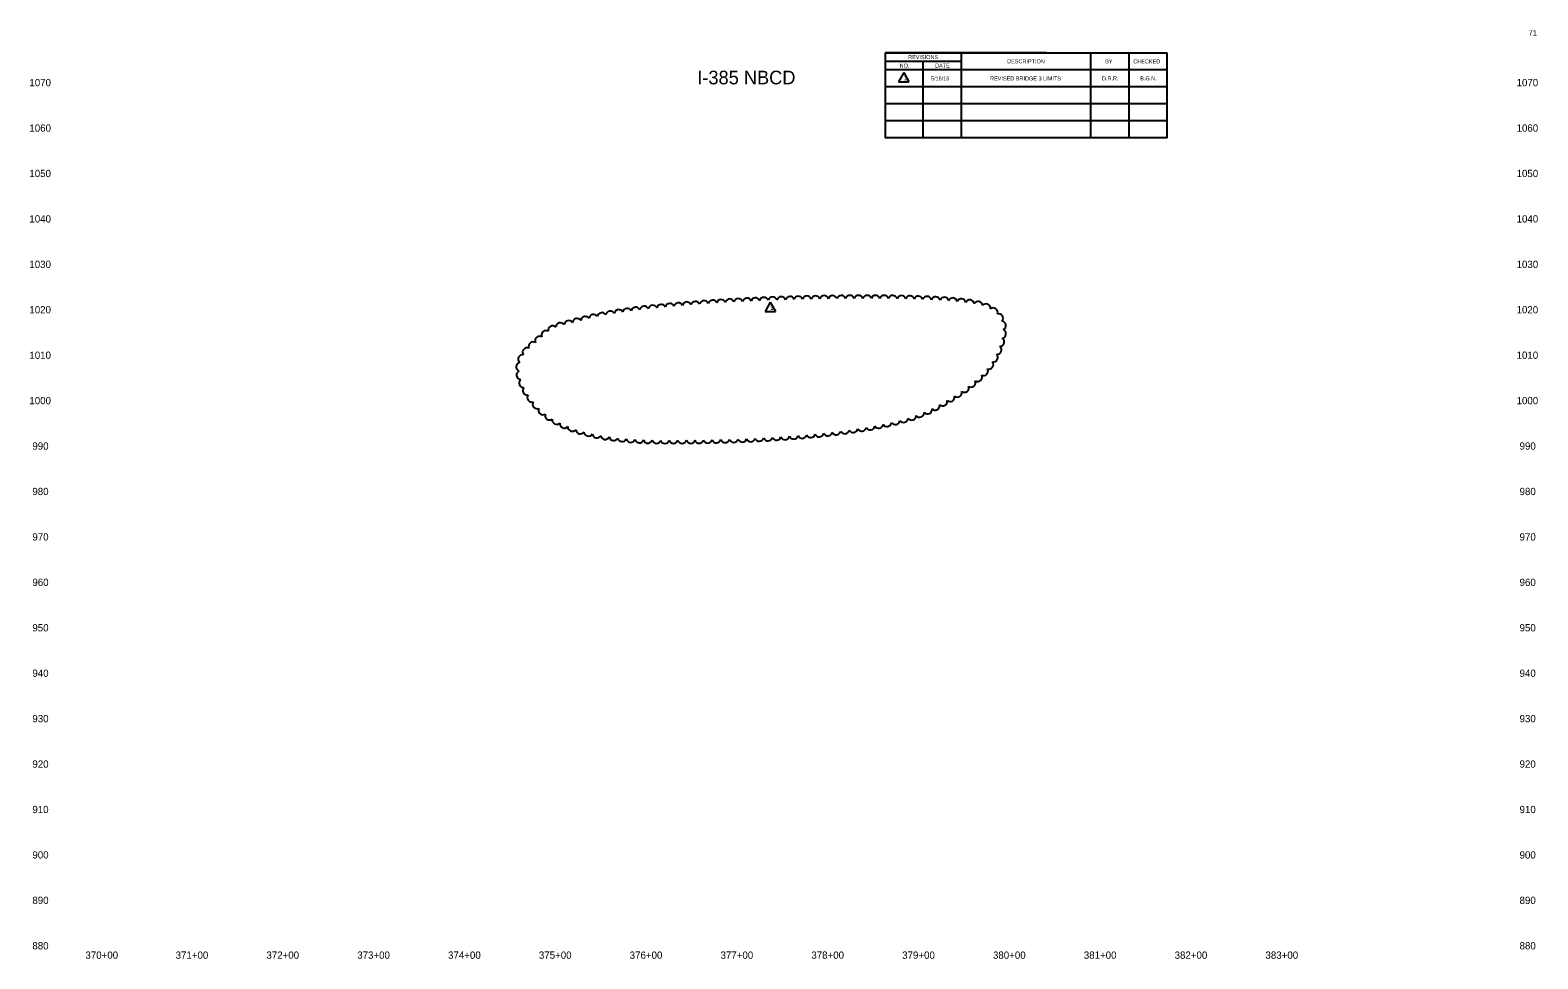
# Model space of a CAD drawing. Extents: x 16977137 to 16978798, y 12564177 to 12565200.
import ezdxf

# ---------------------------------------------------------------- set-up
doc = ezdxf.new("R2010")
doc.units = 0
for name, color, linetype in [('RD_DDB_ElevTX', 7, 'Continuous'), ('RD_DDB_StaTX', 7, 'Continuous'), ('RD_SHT_TX', 7, 'Continuous')]:
    doc.layers.add(name, color=color, linetype=linetype)

msp = doc.modelspace()

# ---------------------------------------------------------------- linework, layer by layer
at = {"layer": 'RD_SHT_TX'}
for p, q in [((16978078.8, 12565174.6), (16978389.4, 12565174.6)), ((16978256, 12565174.6), (16978078.8, 12565174.6)), ((16978078.8, 12565174.6), (16978078.8, 12565081.1)), ((16978162.8, 12565081.1), (16978162.8, 12565174.6)), ((16978305.4, 12565081.1), (16978305.4, 12565174.6)), ((16978347.4, 12565081.1), (16978347.4, 12565174.6)), ((16978389.4, 12565081), (16978389.4, 12565174.5)), ((16978162.8, 12565165.2), (16978078.8, 12565165.2)), ((16978389.4, 12565155.9), (16978078.8, 12565155.9)), ((16978120.8, 12565081.1), (16978120.8, 12565165.2)), ((16978099.4, 12565152.9), (16978093.7, 12565142.7)), ((16978093.7, 12565142.7), (16978105.1, 12565142.7)), ((16978099.4, 12565152.9), (16978105.1, 12565142.7)), ((16978389.4, 12565137.2), (16978078.8, 12565137.2)), ((16978389.4, 12565118.5), (16978078.8, 12565118.5)), ((16978389.4, 12565099.8), (16978078.8, 12565099.8)), ((16978389.4, 12565081), (16978078.8, 12565081.1)), ((16977952.4, 12564900.2), (16977946.8, 12564890)), ((16977946.8, 12564890), (16977958.1, 12564890)), ((16977952.4, 12564900.2), (16977958.1, 12564890))]:
    msp.add_line(p, q, dxfattribs=at)
for centre, radius, start, end in [((16977945.5, 12564900.5), 4.96, 19.8292, 164.8292), ((16977955, 12564900.9), 4.96, 19.6052, 164.6052), ((16977964.4, 12564901.2), 4.96, 19.388, 164.388), ((16977973.9, 12564901.5), 4.96, 19.1772, 164.1772), ((16977983.3, 12564901.8), 4.96, 18.9726, 163.9726), ((16977992.8, 12564902), 4.96, 18.7739, 163.7739), ((16978002.2, 12564902.2), 4.96, 18.5808, 163.5808), ((16978011.7, 12564902.4), 4.96, 18.3931, 163.3931), ((16978021.1, 12564902.5), 4.96, 18.2104, 163.2104), ((16978030.6, 12564902.6), 4.96, 18.0327, 163.0327), ((16978040, 12564902.7), 4.96, 17.8596, 162.8596), ((16978049.5, 12564902.7), 4.96, 17.691, 162.691), ((16978058.9, 12564902.7), 4.96, 17.5232, 162.5232), ((16978068.4, 12564902.7), 4.96, 17.3057, 162.3057), ((16978077.8, 12564902.7), 4.96, 17.0495, 162.0495), ((16978087.3, 12564902.6), 4.96, 16.7608, 161.7608), ((16978096.7, 12564902.4), 4.96, 16.4321, 161.4321), ((16978106.2, 12564902.2), 4.96, 16.0533, 161.0533), ((16978115.6, 12564901.9), 4.96, 15.6101, 160.6101), ((16978125.1, 12564901.6), 4.96, 15.0821, 160.0821), ((16978134.5, 12564901.1), 4.96, 14.4385, 159.4385), ((16978143.9, 12564900.6), 4.96, 13.63, 158.63), ((16977767, 12564883.7), 4.96, 28.648, 173.648), ((16977776.3, 12564885.4), 4.96, 27.371, 172.371), ((16977785.6, 12564887), 4.96, 26.3569, 171.3569), ((16977794.9, 12564888.4), 4.96, 25.5269, 170.5269), ((16977804.2, 12564889.6), 4.96, 24.8317, 169.8317), ((16977813.6, 12564890.8), 4.96, 24.2385, 169.2385), ((16977823, 12564891.8), 4.96, 23.7248, 168.7248), ((16977832.4, 12564892.8), 4.96, 23.2744, 168.2744), ((16977841.8, 12564893.7), 4.96, 22.8752, 167.8752), ((16977851.2, 12564894.6), 4.96, 22.5184, 167.5184), ((16977860.6, 12564895.4), 4.96, 22.1969, 167.1969), ((16977870, 12564896.1), 4.96, 21.9052, 166.9052), ((16977879.5, 12564896.9), 4.96, 21.6204, 166.6204), ((16977888.9, 12564897.5), 4.96, 21.3374, 166.3374), ((16977898.3, 12564898.1), 4.96, 21.0643, 166.0643), ((16977907.8, 12564898.7), 4.96, 20.8005, 165.8005), ((16977917.2, 12564899.2), 4.96, 20.5456, 165.5456), ((16977926.6, 12564899.7), 4.96, 20.299, 165.299), ((16977936.1, 12564900.1), 4.96, 20.0603, 165.0603), ((16978153.3, 12564899.8), 4.96, 12.572, 157.572), ((16978162.7, 12564898.9), 4.96, 11.1037, 156.1037), ((16978172, 12564897.7), 4.96, 8.8691, 153.8691), ((16978181.2, 12564896), 4.96, 4.8448, 149.8448), ((16978190, 12564893.3), 4.96, 356.0223, 141.0223), ((16978197.8, 12564888.9), 4.96, 341.1733, 126.1733), ((16977712.8, 12564869.2), 4.95, 46.5962, 191.5962), ((16977721.1, 12564872.5), 4.96, 31.8949, 176.8949), ((16977730.3, 12564874.9), 4.96, 31.8949, 176.8949), ((16977739.5, 12564877.2), 4.96, 31.8949, 176.8949), ((16977748.6, 12564879.5), 4.96, 31.8309, 176.8309), ((16977757.8, 12564881.8), 4.96, 30.3227, 175.3227), ((16978203.8, 12564882.5), 4.96, 319.3635, 104.3635), ((16978206.8, 12564874.4), 4.96, 296.5873, 81.5873), ((16977691.2, 12564851.4), 4.96, 58.9265, 203.9265), ((16977698.3, 12564857.7), 4.96, 58.9265, 203.9265), ((16977705.4, 12564863.9), 4.96, 58.9265, 203.9265), ((16978205.1, 12564856.4), 4.96, 271.5015, 56.5015), ((16978207, 12564865.4), 4.96, 280.3509, 65.3509), ((16977679.8, 12564837.4), 4.96, 83.1268, 228.1268), ((16977684.6, 12564844.9), 4.96, 65.8967, 210.8967), ((16978198, 12564839.3), 4.96, 258.3928, 43.3928), ((16978202.1, 12564847.7), 4.96, 265.0679, 50.0679), ((16977677.5, 12564828.9), 4.96, 102.4985, 247.4985), ((16977678, 12564819.9), 4.96, 118.7219, 263.7219), ((16978187.2, 12564824.3), 4.96, 245.3556, 30.3556), ((16978193.1, 12564831.5), 4.96, 251.7368, 36.7368), ((16977680.7, 12564811.2), 4.96, 130.0537, 275.0537), ((16977684.8, 12564802.9), 4.96, 137.7212, 282.7212), ((16978166.1, 12564805.9), 4.96, 233.4335, 18.4335), ((16978173.5, 12564811.6), 4.96, 236.1845, 21.1845), ((16978180.7, 12564817.7), 4.96, 239.6683, 24.6683), ((16977689.8, 12564795.1), 4.96, 143.0904, 288.0904), ((16977695.6, 12564787.8), 4.96, 148.0439, 293.0439), ((16978142.3, 12564790.8), 4.96, 226.919, 11.919), ((16978150.4, 12564795.6), 4.96, 228.844, 13.844), ((16978158.3, 12564800.6), 4.96, 231.0021, 16.0021), ((16977702, 12564781.2), 4.96, 155.8506, 300.8506), ((16977709.3, 12564775.5), 4.96, 162.8917, 307.8917), ((16978099.2, 12564772.7), 4.96, 213.0669, 358.0669), ((16978108.2, 12564775.4), 4.96, 215.3678, 0.3678), ((16978117, 12564778.5), 4.96, 218.3921, 3.3921), ((16978125.6, 12564782.1), 4.96, 222.4938, 7.4938), ((16978134, 12564786.3), 4.96, 225.1937, 10.1937), ((16977717.2, 12564770.6), 4.96, 168.7796, 313.7796), ((16977725.6, 12564766.5), 4.96, 173.6557, 318.6557), ((16977734.3, 12564763), 4.96, 177.6994, 322.6994), ((16977743.2, 12564760.1), 4.96, 181.0771, 326.0771), ((16977752.2, 12564757.7), 4.96, 183.9262, 328.9262), ((16978006.3, 12564756.9), 4.96, 203.3677, 348.3677), ((16978015.7, 12564758), 4.96, 203.9101, 348.9101), ((16978025, 12564759.1), 4.96, 204.4827, 349.4827), ((16978034.4, 12564760.3), 4.96, 205.1018, 350.1018), ((16978043.8, 12564761.6), 4.96, 205.7969, 350.7969), ((16978053.1, 12564763), 4.96, 206.5847, 351.5847), ((16978062.4, 12564764.5), 4.96, 207.4871, 352.4871), ((16978071.7, 12564766.3), 4.96, 208.534, 353.534), ((16978080.9, 12564768.2), 4.96, 209.7675, 354.7675), ((16978090.1, 12564770.3), 4.96, 211.2481, 356.2481), ((16977761.4, 12564755.7), 4.96, 186.355, 331.355), ((16977770.7, 12564754), 4.96, 188.4473, 333.4473), ((16977780, 12564752.7), 4.96, 190.2674, 335.2674), ((16977789.3, 12564751.6), 4.96, 191.8652, 336.8652), ((16977798.7, 12564750.8), 4.96, 193.2794, 338.2794), ((16977808.1, 12564750.2), 4.96, 194.5406, 339.5406), ((16977817.5, 12564749.8), 4.96, 195.673, 340.673), ((16977827, 12564749.6), 4.96, 196.6959, 341.6959), ((16977836.4, 12564749.5), 4.96, 197.4851, 342.4851), ((16977845.9, 12564749.6), 4.96, 197.7388, 342.7388), ((16977855.3, 12564749.6), 4.96, 197.9565, 342.9565), ((16977864.8, 12564749.7), 4.96, 198.1833, 343.1833), ((16977874.2, 12564749.8), 4.96, 198.42, 343.42), ((16977883.7, 12564750), 4.96, 198.6672, 343.6672), ((16977893.1, 12564750.2), 4.96, 198.9257, 343.9257), ((16977902.6, 12564750.5), 4.96, 199.1965, 344.1965), ((16977912, 12564750.8), 4.96, 199.4805, 344.4805), ((16977921.5, 12564751.1), 4.96, 199.7787, 344.7787), ((16977930.9, 12564751.5), 4.96, 200.0925, 345.0925), ((16977940.3, 12564752), 4.96, 200.4231, 345.4231), ((16977949.8, 12564752.5), 4.96, 200.7721, 345.7721), ((16977959.2, 12564753.1), 4.96, 201.1412, 346.1412), ((16977968.6, 12564753.7), 4.96, 201.5324, 346.5324), ((16977978, 12564754.4), 4.96, 201.9479, 346.9479), ((16977987.5, 12564755.2), 4.96, 202.3902, 347.3902), ((16977996.9, 12564756), 4.96, 202.8624, 347.8624)]:
    msp.add_arc(centre, radius, start, end, dxfattribs=at)

# ---------------------------------------------------------------- texts
at = {"layer": 'RD_DDB_ElevTX'}
for s, p in [('1070', (16977136.6, 12565137.8)), ('1070', (16978774.1, 12565137.8)), ('1060', (16977136.6, 12565087.8)), ('1060', (16978774.1, 12565087.8)), ('1050', (16977136.6, 12565037.8)), ('1050', (16978774.1, 12565037.8)), ('1040', (16977136.6, 12564987.8)), ('1040', (16978774.1, 12564987.8)), ('1030', (16977136.6, 12564937.8)), ('1030', (16978774.1, 12564937.8)), ('1020', (16977136.6, 12564887.8)), ('1020', (16978774.1, 12564887.8)), ('1010', (16977136.6, 12564837.8)), ('1010', (16978774.1, 12564837.8)), ('1000', (16977136.6, 12564787.8)), ('1000', (16978774.1, 12564787.8)), ('990', (16977139.9, 12564737.8)), ('990', (16978777.4, 12564737.8)), ('980', (16977139.9, 12564687.8)), ('980', (16978777.4, 12564687.8)), ('970', (16977139.9, 12564637.8)), ('970', (16978777.4, 12564637.8)), ('960', (16977139.9, 12564587.8)), ('960', (16978777.4, 12564587.8)), ('950', (16977139.9, 12564537.8)), ('950', (16978777.4, 12564537.8)), ('940', (16977139.9, 12564487.8)), ('940', (16978777.4, 12564487.8)), ('930', (16977139.9, 12564437.8)), ('930', (16978777.4, 12564437.8)), ('920', (16977139.9, 12564387.8)), ('920', (16978777.4, 12564387.8)), ('910', (16977139.9, 12564337.8)), ('910', (16978777.4, 12564337.8)), ('900', (16977139.9, 12564287.8)), ('900', (16978777.4, 12564287.8)), ('890', (16977139.9, 12564237.8)), ('890', (16978777.4, 12564237.8)), ('880', (16977139.9, 12564187.8)), ('880', (16978777.4, 12564187.8))]:
    msp.add_text(s, height=8, dxfattribs=at).set_placement(p)
at = {"layer": 'RD_DDB_StaTX'}
for s, p in [('370+00', (16977198.3, 12564177.5)), ('371+00', (16977297.6, 12564177.5)), ('372+00', (16977397.6, 12564177.5)), ('373+00', (16977497.6, 12564177.5)), ('374+00', (16977597.6, 12564177.5)), ('375+00', (16977697.6, 12564177.5)), ('376+00', (16977797.6, 12564177.5)), ('377+00', (16977897.6, 12564177.5)), ('378+00', (16977997.6, 12564177.5)), ('379+00', (16978097.6, 12564177.5)), ('380+00', (16978197.6, 12564177.5)), ('381+00', (16978297.6, 12564177.5)), ('382+00', (16978397.6, 12564177.5)), ('383+00', (16978497.6, 12564177.5))]:
    msp.add_text(s, height=8, dxfattribs=at).set_placement(p)
at = {"layer": 'RD_SHT_TX'}
for s, height, p in [('71', 6, (16978787.3, 12565193.5)), ('REVISIONS', 4.4, (16978104.1, 12565167.7)), ('I-385 NBCD', 15, (16977872, 12565139.9)), ('NO.', 4.4, (16978094.8, 12565158.3)), ('CHECKED', 4.4, (16978352.1, 12565163)), ('1', 4.4, (16978099.4, 12565144.4)), ('5/16/16', 4.4, (16978129.3, 12565144.2)), ('REVISED BRIDGE 3 LIMITS', 4.4, (16978194.4, 12565144.2)), ('D.R.R.', 4.4, (16978317.6, 12565144.2)), ('B.G.N.', 4.4, (16978359.7, 12565144.2)), ('1', 4.4, (16977952.4, 12564891.7))]:
    msp.add_text(s, height=height, dxfattribs=at).set_placement(p)
for s, height, p in [('DATE', 4.41, (16978133.8, 12565158.4)), ('DESCRIPTION', 4.408, (16978213.1, 12565163.1)), ('BY', 4.41, (16978321.1, 12565163))]:
    msp.add_text(s, height=height, rotation=359.7246, dxfattribs=at).set_placement(p)

doc.saveas('drawing.dxf')
